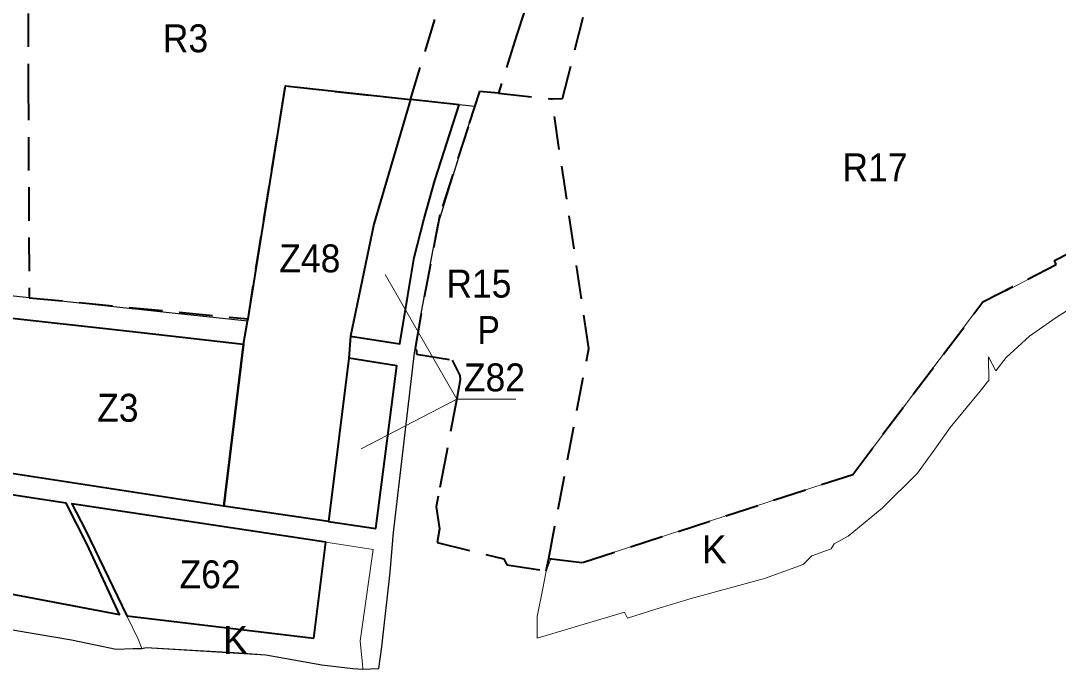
# Model space of a CAD drawing. Extents: x -650276 to -642489, y -1074311 to -1066658.
# Drawn here: x -647038 to -646145, y -1069854 to -1069297 of the extents above; entities that cross this region are included whole.
import ezdxf

# ---------------------------------------------------------------- set-up
doc = ezdxf.new("R2010")
doc.units = 0
doc.header["$LTSCALE"] = 9.6
doc.linetypes.add('MEDIUM_DASHED', pattern=[4.5, 3, -1.5])
for name, color, linetype, lineweight in [('42', 7, 'Continuous', 25), ('44', 7, 'Continuous', 40), ('45', 7, 'Continuous', 40), ('46', 7, 'Continuous', 13), ('47', 7, 'Continuous', 13), ('48', 7, 'Continuous', 35), ('60', 7, 'Continuous', 35), ('61', 7, 'MEDIUM_DASHED', 40), ('62', 7, 'Continuous', 35)]:
    doc.layers.add(name, color=color, linetype=linetype, lineweight=lineweight)

msp = doc.modelspace()

# ---------------------------------------------------------------- linework, layer by layer
at = {"layer": '42'}
msp.add_lwpolyline([(-647060.029, -1069817.854), (-646993.81, -1069829.12), (-646993.81, -1069829.12), (-646955.45, -1069836.93), (-646940.94, -1069836.34), (-646933.39, -1069836.51), (-646929.67, -1069835.68), (-646826.63, -1069841.84), (-646778.74, -1069850.44), (-646751.8, -1069853.72), (-646743.31, -1069854.26), (-646729.54, -1069853.69), (-646727.09, -1069835.05), (-646719.79, -1069770.87), (-646716.98, -1069736.73), (-646698.96, -1069582.26), (-646698.96, -1069582.26), (-646698.4, -1069578.93), (-646693.58, -1069550.28), (-646679.13, -1069473.51), (-646647.141, -1069370.826), (-646702.425, -1069364.771), (-646809.879, -1069353.002), (-646842.103, -1069553.182), (-646842.441, -1069555.283), (-646910.029, -1069548.006), (-646986.633, -1069539.757), (-647046.325, -1069533.275)], dxfattribs=at)
at = {"layer": '44'}
msp.add_line((-646772.907, -1069727.177), (-646732.143, -1069733.308), dxfattribs=at)
msp.add_lwpolyline([(-646660.526, -1069369.36), (-646702.425, -1069364.771), (-646733.74, -1069471.688), (-646754.066, -1069567.993), (-646711.442, -1069574.759), (-646704.68, -1069533.06), (-646699.07, -1069500.57), (-646690.51, -1069466.97), (-646681.5, -1069434.17)], close=True, dxfattribs=at)
at = {"layer": '44', "lineweight": 13}
msp.add_lwpolyline([(-646611.673, -1069622.045), (-646662.372, -1069622.045), (-646744.747, -1069664.938), (-646662.372, -1069622.045), (-646723.996, -1069515.165)], dxfattribs=at)
at = {"layer": '44'}
for points in [[(-646725.82, -1069684.5), (-646714.037, -1069593.585), (-646755.269, -1069587.04), (-646772.907, -1069727.177)], [(-646732.143, -1069733.308), (-646725.82, -1069684.5), (-646725.82, -1069684.5)]]:
    msp.add_lwpolyline(points, dxfattribs=at)
at = {"layer": '45'}
for points in [[(-646842.441, -1069555.283), (-646842.103, -1069553.182), (-646809.879, -1069353.002), (-646702.425, -1069364.771), (-646702.425, -1069364.771), (-646702.425, -1069364.771), (-646702.425, -1069364.771), (-646702.425, -1069364.771), (-646733.74, -1069471.688), (-646733.74, -1069471.688), (-646754.066, -1069567.993)], [(-646842.441, -1069555.283), (-646842.103, -1069553.182), (-646809.879, -1069353.002), (-646702.425, -1069364.771), (-646702.425, -1069364.771), (-646702.425, -1069364.771), (-646702.425, -1069364.771), (-646702.425, -1069364.771), (-646733.74, -1069471.688), (-646733.74, -1069471.688), (-646754.066, -1069567.993)], [(-646754.066, -1069567.993), (-646755.269, -1069587.04), (-646772.906, -1069727.176), (-646863, -1069714), (-646846, -1069575), (-646842.441, -1069555.283)], [(-646754.066, -1069567.993), (-646755.269, -1069587.04), (-646772.906, -1069727.176), (-646863, -1069714), (-646846, -1069575), (-646842.441, -1069555.283)]]:
    msp.add_lwpolyline(points, dxfattribs=at)
for points in [[(-647060.7, -1069683.894), (-647061.304, -1069551.773), (-647047.648, -1069552.245), (-646944.168, -1069563.743), (-646846, -1069575), (-646863, -1069714)], [(-647060.7, -1069683.894), (-647061.304, -1069551.773), (-647047.648, -1069552.245), (-646944.168, -1069563.743), (-646846, -1069575), (-646863, -1069714)], [(-647060.617, -1069702.116), (-647082.682, -1069698.791), (-647089.456, -1069698.579), (-647135.585, -1069697.137), (-647156.782, -1069698.901), (-647154.33, -1069729.69), (-647150.138, -1069782.334), (-647105.334, -1069785.168), (-647082.271, -1069788.81), (-647060.23, -1069786.932), (-646952.56, -1069807.13), (-646980.4, -1069746.98), (-646998.56, -1069711.443)], [(-646785.437, -1069827.534), (-646775.286, -1069745.022), (-646993.771, -1069712.163), (-646981.92, -1069734.86), (-646946.369, -1069808.291)], [(-646785.437, -1069827.534), (-646775.286, -1069745.022), (-646993.771, -1069712.163), (-646981.92, -1069734.86), (-646946.369, -1069808.291)]]:
    msp.add_lwpolyline(points, close=True, dxfattribs=at)
at = {"layer": '47'}
for points in [[(-646023.96, -1069440.34), (-646028.16, -1069441.58), (-646080.35, -1069469.89), (-646102.15, -1069479.49), (-646148.5, -1069503), (-646146.8, -1069506.6), (-646189.17, -1069528.74), (-646209.9, -1069538.5), (-646321.973, -1069686.855), (-646554.262, -1069762.602), (-646581.489, -1069759.421), (-646585.51, -1069769.57)], [(-646491.18, -1069802.78), (-646491.18, -1069802.78), (-646460.97, -1069793.56), (-646397.74, -1069776.29), (-646364.67, -1069764.23), (-646357, -1069756.7), (-646340.48, -1069750.92), (-646337.97, -1069746.4), (-646325.92, -1069740.05), (-646296.64, -1069715.72), (-646266.27, -1069685.75), (-646250, -1069663.09), (-646238.19, -1069646.63), (-646212.43, -1069615.33), (-646210.03, -1069612.42), (-646205.9, -1069607.17), (-646205, -1069606.03), (-646205.25, -1069585.67), (-646198.82, -1069597.83), (-646190.07, -1069586.48), (-646169.9, -1069568.04), (-646146.81, -1069551.97), (-646129.87, -1069541.19)], [(-646778.74, -1069850.44), (-646751.8, -1069853.72), (-646743.31, -1069854.26), (-646743.7, -1069850.07), (-646745.56, -1069829.84), (-646743.85, -1069817.72), (-646734.48, -1069751.35), (-646775.286, -1069745.022), (-646785.437, -1069827.534), (-646946.369, -1069808.291), (-646936.6, -1069828.47), (-646933.39, -1069836.51)], [(-646585.51, -1069769.57), (-646588.25, -1069783.37), (-646593.34, -1069808.99), (-646593.34, -1069827.68)], [(-646593.34, -1069827.68), (-646518.19, -1069805.27), (-646515.63, -1069810.24), (-646491.18, -1069802.78)], [(-646933.39, -1069836.51), (-646933.39, -1069836.51), (-646929.67, -1069835.68), (-646875, -1069838.65), (-646853.88, -1069839.8), (-646826.63, -1069841.84), (-646778.74, -1069850.44), (-646778.74, -1069850.44)]]:
    msp.add_lwpolyline(points, dxfattribs=at)
at = {"layer": '61'}
msp.add_line((-646626.774, -1069359.349), (-646642.89, -1069357.68), dxfattribs=at)
for points in [[(-646583.457, -1069759.191), (-646554.262, -1069762.602), (-646321.973, -1069686.855), (-646209.9, -1069538.5), (-646146.8, -1069506.6), (-646148.5, -1069503), (-646028.16, -1069441.58), (-646023.96, -1069440.34), (-646075.49, -1069318.19), (-646025.14, -1069285.394), (-646153.307, -1069059.947)], [(-646642.89, -1069357.68), (-646652.72, -1069388.08), (-646677.18, -1069463.79), (-646693.58, -1069550.28), (-646698.4, -1069578.93), (-646697.31, -1069579.97), (-646697.31, -1069583.47), (-646666.36, -1069588.57), (-646659.83, -1069601.8), (-646659.52, -1069605.53), (-646662.57, -1069621.66), (-646671.69, -1069669.92), (-646678.52, -1069705.63), (-646680.28, -1069714.83), (-646677.36, -1069733.65), (-646679.46, -1069745.37), (-646622, -1069759.34), (-646619.49, -1069764.46), (-646585.51, -1069769.57), (-646583.457, -1069759.191), (-646548.91, -1069578.56), (-646580.797, -1069364.111)]]:
    msp.add_lwpolyline(points, dxfattribs=at)
for points in [[(-646572.586, -1069194.485), (-646577.878, -1069206.485), (-646611.107, -1069309.68), (-646626.774, -1069359.349), (-646580.797, -1069364.111), (-646571.479, -1069363.822), (-646526.31, -1069184.381), (-646570.296, -1069190.776)], [(-647031.152, -1069204.288), (-647031.152, -1069353.712), (-647030.324, -1069535.053), (-646842.103, -1069553.182), (-646809.879, -1069353.002), (-646702.425, -1069364.771), (-646659.946, -1069226.375), (-646874.542, -1069206.4)]]:
    msp.add_lwpolyline(points, close=True, dxfattribs=at)

# ---------------------------------------------------------------- texts
at = {"layer": '44', "width": 0.95}
msp.add_text('Z82', height=24, dxfattribs=at).set_placement((-646656.364, -1069615.463))
at = {"layer": '46', "width": 0.95}
for s, p in [('Z48', (-646815.179, -1069513.185)), ('Z48', (-646815.179, -1069513.185)), ('Z3', (-646971.871, -1069641.589)), ('Z3', (-646971.871, -1069641.589)), ('Z62', (-646900.991, -1069784.684)), ('Z62', (-646900.991, -1069784.684))]:
    msp.add_text(s, height=24, dxfattribs=at).set_placement(p)
at = {"layer": '48'}
for p in [(-646451.743, -1069763.13), (-646451.743, -1069763.13), (-646863.536, -1069841.154)]:
    msp.add_text('K', height=24, dxfattribs=at).set_placement(p)
at = {"layer": '60', "width": 0.9}
msp.add_text('P', height=24, dxfattribs=at).set_placement((-646644.717, -1069574.793))
msp.add_text('P', height=24, dxfattribs=at).set_placement((-646644.717, -1069574.793))
at = {"layer": '62', "width": 0.95}
for s, p in [('R3', (-646915.354, -1069324.087)), ('R3', (-646915.354, -1069324.087)), ('R17', (-646330.736, -1069434.917)), ('R15', (-646671.455, -1069534.875)), ('R15', (-646671.455, -1069534.875))]:
    msp.add_text(s, height=24, dxfattribs=at).set_placement(p)

doc.saveas('drawing.dxf')
